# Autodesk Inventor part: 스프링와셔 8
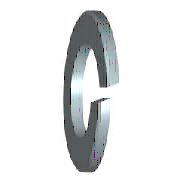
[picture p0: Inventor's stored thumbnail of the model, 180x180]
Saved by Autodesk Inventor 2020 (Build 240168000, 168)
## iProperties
Created: 2012-02
Part Number: 스프링와셔 8
Material: 강철, 연강
Description: 스프링 잠금 와셔
Document SubType Name: Modeling
Standard: KS B 1324
Designer: mduedu
Standards Organization: KS
Language: ko-KR
Size Designation: 번호 3 - 8
Categories: <MemberInstance><Categories><Category DisplayName="조임쇠" InternalName="e4da775c-781d-43d5-af7c-5136215cf5a6" Mnemonic="FSTN"><Category DisplayName="와셔" InternalN
Density: 7.86 g/cm^3
Mass: 2.27751 g
Surface Area: 4.25113 cm^2
Volume: 0.289759 cm^3
Appearance: 파란색 - 벽 페인트 - 광택
IsCustomPart: 1
Author: mduedu
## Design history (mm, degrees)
sketch "스케치1"
  geometry: C1 r 7.4 at (0, 0); C2 r 4.1 at (0, 0); 1 further point
  constraints: 2 centre point, 2 coincident
  dimensions: "d0" = 8.2 diameter of C2 (= SD1); "d1" = 14.8 diameter of C1 (= SD2)
extrude "본체" new body sketch "스케치1" distance "d2" = 2.5 (= SD); taper "d3" = 0 deg
sketch "스케치2"
  geometry: L1 (0, -4.1)-(0, 4.1) reference; L2 (2.5, 7.4)-(2.5, -7.4) reference; L3 (-1.2, 0)-(7.2, 0) reference; L4 (0, -0.5)-(2.5, 0.41); L5 (0, 0.5)-(2.5, 1.41)
  constraints: 4 end point, 4 point on line, 1 parallel
  dimensions: "d4" = 0.5 distance from line of L3 L4.start (= 0.2 x SD); "d5" = 0.5 distance from line of L3 L5.start (= 0.2 x SD); "d6" = 70 deg angle of L2 L4 (= FAWI)
extrude "절단부" cut sketch "스케치2" stored distance "d7" = 2.5 (= SD); taper "d8" = 0 deg
workaxis "Work Axis1"
workplane "Work Plane1"
body "Solid1"
other parameters: "SD1" = 8.2 [user parameter; used in 1 equation term], "SD2" = 14.8 [user parameter; used in 1 equation term], "SD" = 2.5 [user parameter; used in 4 equation terms], "FAWI" = 70 deg [user parameter; used in 1 equation term], "d9" = 0, "d10" = 0, "d11" = 0, "d12" = 0, "SDI" = 3.3 [user parameter], "NND" = 8 [user parameter]
